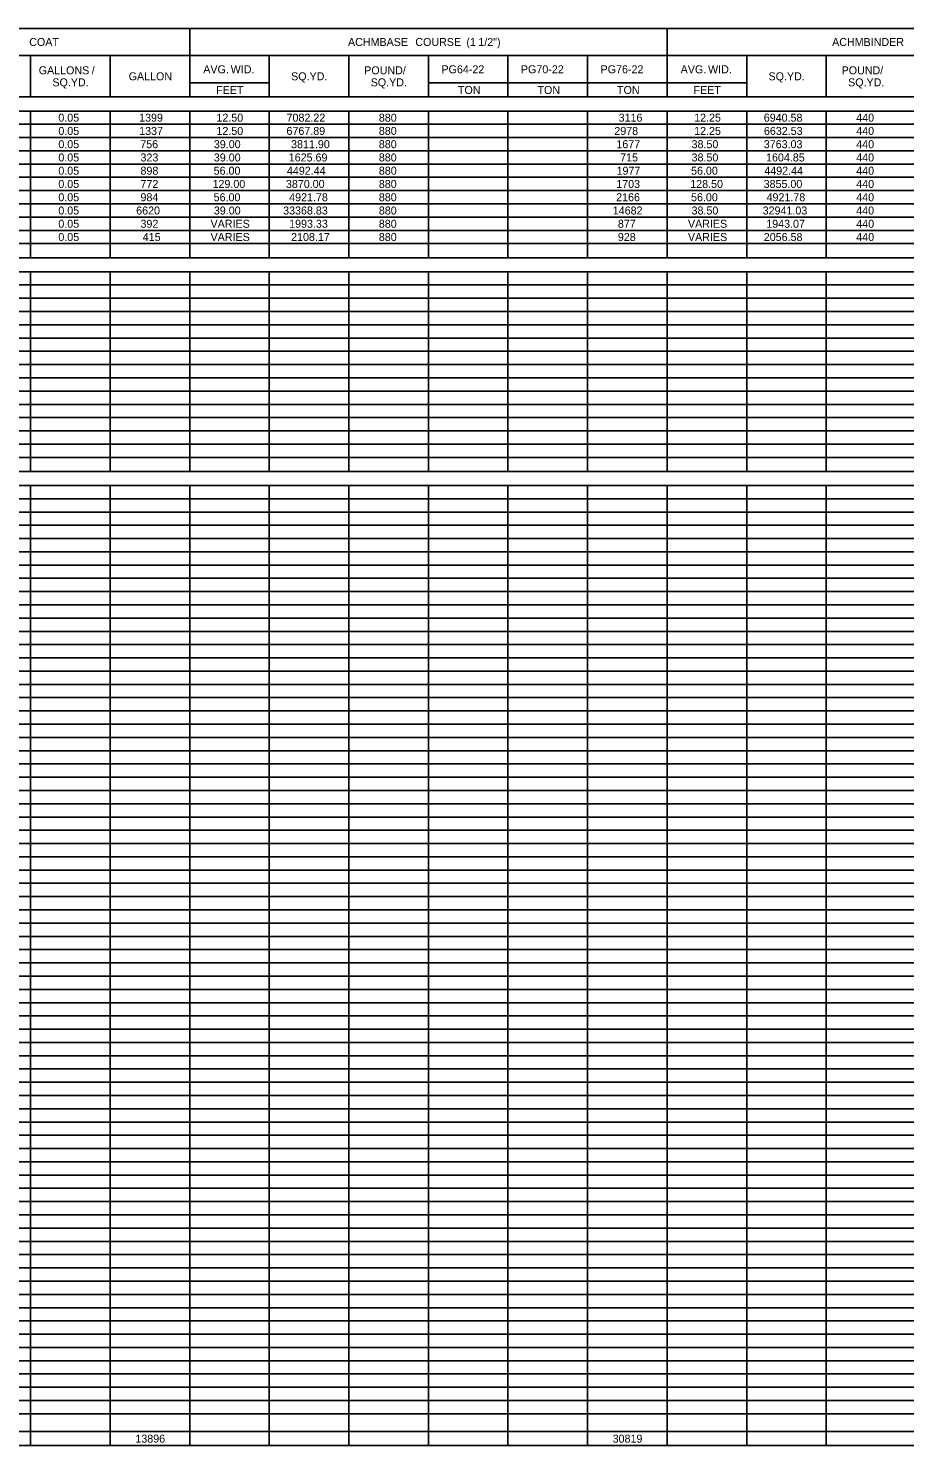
# Model space of a CAD drawing. Extents: x 1226590 to 1228573, y 151304 to 154224.
# Drawn here: x 1227054 to 1227485, y 151485 to 152182 of the extents above; entities that cross this region are included whole.
import ezdxf

# ---------------------------------------------------------------- set-up
doc = ezdxf.new("R2010")
doc.units = 0
doc.layers.add('R_Dimension', color=7, linetype='Continuous')

msp = doc.modelspace()

# ---------------------------------------------------------------- linework, layer by layer
at = {"layer": 'R_Dimension'}
for p, q in [((1226590.27, 152182.03), (1228150.73, 152182.03)), ((1227133.19, 152148.27), (1227133.19, 152182.03)), ((1227368.01, 152148.27), (1227368.01, 152182.03)), ((1226898.37, 152168.6), (1228150.73, 152168.6)), ((1227054.92, 152148.27), (1227054.92, 152168.6)), ((1227094.05, 152148.27), (1227094.05, 152168.6)), ((1227172.32, 152148.27), (1227172.32, 152168.6)), ((1227211.46, 152148.27), (1227211.46, 152168.6)), ((1227250.6, 152148.27), (1227250.6, 152168.6)), ((1227289.73, 152148.27), (1227289.73, 152168.6)), ((1227328.87, 152148.27), (1227328.87, 152168.6)), ((1227407.14, 152148.27), (1227407.14, 152168.6)), ((1227446.28, 152148.27), (1227446.28, 152168.6)), ((1227133.19, 152155.17), (1227172.32, 152155.17)), ((1227250.6, 152155.17), (1227407.14, 152155.17)), ((1226590.27, 152148.27), (1228150.73, 152148.27)), ((1227015.78, 152148.27), (1227172.32, 152148.27)), ((1227172.32, 152148.27), (1227407.14, 152148.27)), ((1227407.14, 152148.27), (1227641.96, 152148.27)), ((1226590.27, 152141.36), (1228150.73, 152141.36)), ((1227054.92, 152069.23), (1227054.92, 152141.36)), ((1227094.05, 152069.23), (1227094.05, 152141.36)), ((1227133.19, 152069.23), (1227133.19, 152141.36)), ((1227172.32, 152069.23), (1227172.32, 152141.36)), ((1227211.46, 152069.23), (1227211.46, 152141.36)), ((1227250.6, 152069.23), (1227250.6, 152141.36)), ((1227289.73, 152069.23), (1227289.73, 152141.36)), ((1227328.87, 152069.23), (1227328.87, 152141.36)), ((1227368.01, 152069.23), (1227368.01, 152141.36)), ((1227407.14, 152069.23), (1227407.14, 152141.36)), ((1227446.28, 152069.23), (1227446.28, 152141.36)), ((1226590.27, 152134.84), (1228150.73, 152134.84)), ((1226590.27, 152128.31), (1228150.73, 152128.31)), ((1226590.27, 152121.79), (1228150.73, 152121.79)), ((1226590.27, 152115.27), (1228150.73, 152115.27)), ((1226590.27, 152108.75), (1228150.73, 152108.75)), ((1226590.27, 152102.22), (1228150.73, 152102.22)), ((1226590.27, 152095.7), (1228150.73, 152095.7)), ((1226590.27, 152089.18), (1228150.73, 152089.18)), ((1226590.27, 152082.65), (1228150.73, 152082.65)), ((1226590.27, 152076.13), (1228150.73, 152076.13)), ((1226590.27, 152069.23), (1228150.73, 152069.23)), ((1226590.27, 152062.32), (1228150.73, 152062.32)), ((1227054.92, 151964.1), (1227054.92, 152062.32)), ((1227094.05, 151964.1), (1227094.05, 152062.32)), ((1227133.19, 151964.1), (1227133.19, 152062.32)), ((1227172.32, 151964.1), (1227172.32, 152062.32)), ((1227211.46, 151964.1), (1227211.46, 152062.32)), ((1227250.6, 151964.1), (1227250.6, 152062.32)), ((1227289.73, 151964.1), (1227289.73, 152062.32)), ((1227328.87, 151964.1), (1227328.87, 152062.32)), ((1227368.01, 151964.1), (1227368.01, 152062.32)), ((1227407.14, 151964.1), (1227407.14, 152062.32)), ((1227446.28, 151964.1), (1227446.28, 152062.32)), ((1226590.27, 152055.8), (1228150.73, 152055.8)), ((1226590.27, 152049.27), (1228150.73, 152049.27)), ((1226590.27, 152042.75), (1228150.73, 152042.75)), ((1226590.27, 152036.23), (1228150.73, 152036.23)), ((1226590.27, 152029.71), (1228150.73, 152029.71)), ((1226590.27, 152023.18), (1228150.73, 152023.18)), ((1226590.27, 152016.66), (1228150.73, 152016.66)), ((1226590.27, 152010.14), (1228150.73, 152010.14)), ((1226590.27, 152003.61), (1228150.73, 152003.61)), ((1226590.27, 151997.09), (1228150.73, 151997.09)), ((1226590.27, 151990.57), (1228150.73, 151990.57)), ((1226590.27, 151984.05), (1228150.73, 151984.05)), ((1226590.27, 151977.52), (1228150.73, 151977.52)), ((1226590.27, 151971), (1228150.73, 151971)), ((1226590.27, 151964.1), (1228150.73, 151964.1)), ((1226590.27, 151957.19), (1228150.73, 151957.19)), ((1227054.92, 151484.92), (1227054.92, 151957.19)), ((1227094.05, 151484.92), (1227094.05, 151957.19)), ((1227133.19, 151484.92), (1227133.19, 151957.19)), ((1227172.32, 151484.92), (1227172.32, 151957.19)), ((1227211.46, 151484.92), (1227211.46, 151957.19)), ((1227250.6, 151484.92), (1227250.6, 151957.19)), ((1227289.73, 151484.92), (1227289.73, 151957.19)), ((1227328.87, 151484.92), (1227328.87, 151957.19)), ((1227368.01, 151484.92), (1227368.01, 151957.19)), ((1227407.14, 151484.92), (1227407.14, 151957.19)), ((1227446.28, 151484.92), (1227446.28, 151957.19)), ((1226590.27, 151950.67), (1228150.73, 151950.67)), ((1226590.27, 151944.14), (1228150.73, 151944.14)), ((1226590.27, 151937.62), (1228150.73, 151937.62)), ((1226590.27, 151931.1), (1228150.73, 151931.1)), ((1226590.27, 151924.58), (1228150.73, 151924.58)), ((1226590.27, 151918.05), (1228150.73, 151918.05)), ((1226590.27, 151911.53), (1228150.73, 151911.53)), ((1226590.27, 151905.01), (1228150.73, 151905.01)), ((1226590.27, 151898.48), (1228150.73, 151898.48)), ((1226590.27, 151891.96), (1228150.73, 151891.96)), ((1226590.27, 151885.44), (1228150.73, 151885.44)), ((1226590.27, 151878.92), (1228150.73, 151878.92)), ((1226590.27, 151872.39), (1228150.73, 151872.39)), ((1226590.27, 151865.87), (1228150.73, 151865.87)), ((1226590.27, 151859.35), (1228150.73, 151859.35)), ((1226590.27, 151852.83), (1228150.73, 151852.83)), ((1226590.27, 151846.3), (1228150.73, 151846.3)), ((1226590.27, 151839.78), (1228150.73, 151839.78)), ((1226590.27, 151833.26), (1228150.73, 151833.26)), ((1226590.27, 151826.73), (1228150.73, 151826.73)), ((1226590.27, 151820.21), (1228150.73, 151820.21)), ((1226590.27, 151813.69), (1228150.73, 151813.69)), ((1226590.27, 151807.17), (1228150.73, 151807.17)), ((1226590.27, 151800.64), (1228150.73, 151800.64)), ((1226590.27, 151794.12), (1228150.73, 151794.12)), ((1226590.27, 151787.6), (1228150.73, 151787.6)), ((1226590.27, 151781.08), (1228150.73, 151781.08)), ((1226590.27, 151774.55), (1228150.73, 151774.55)), ((1226590.27, 151768.03), (1228150.73, 151768.03)), ((1226590.27, 151761.51), (1228150.73, 151761.51)), ((1226590.27, 151754.99), (1228150.73, 151754.99)), ((1226590.27, 151748.46), (1228150.73, 151748.46)), ((1226590.27, 151741.94), (1228150.73, 151741.94)), ((1226590.27, 151735.42), (1228150.73, 151735.42)), ((1226590.27, 151728.89), (1228150.73, 151728.89)), ((1226590.27, 151722.37), (1228150.73, 151722.37)), ((1226590.27, 151715.85), (1228150.73, 151715.85)), ((1226590.27, 151709.33), (1228150.73, 151709.33)), ((1226590.27, 151702.8), (1228150.73, 151702.8)), ((1226590.27, 151696.28), (1228150.73, 151696.28)), ((1226590.27, 151689.76), (1228150.73, 151689.76)), ((1226590.27, 151683.24), (1228150.73, 151683.24)), ((1226590.27, 151676.71), (1228150.73, 151676.71)), ((1226590.27, 151670.19), (1228150.73, 151670.19)), ((1226590.27, 151663.67), (1228150.73, 151663.67)), ((1226590.27, 151657.14), (1228150.73, 151657.14)), ((1226590.27, 151650.62), (1228150.73, 151650.62)), ((1226590.27, 151644.1), (1228150.73, 151644.1)), ((1226590.27, 151637.58), (1228150.73, 151637.58)), ((1226590.27, 151631.05), (1228150.73, 151631.05)), ((1226590.27, 151624.53), (1228150.73, 151624.53)), ((1226590.27, 151618.01), (1228150.73, 151618.01)), ((1226590.27, 151611.49), (1228150.73, 151611.49)), ((1226590.27, 151604.96), (1228150.73, 151604.96)), ((1226590.27, 151598.44), (1228150.73, 151598.44)), ((1226590.27, 151591.92), (1228150.73, 151591.92)), ((1226590.27, 151585.4), (1228150.73, 151585.4)), ((1226590.27, 151578.87), (1228150.73, 151578.87)), ((1226590.27, 151572.35), (1228150.73, 151572.35)), ((1226590.27, 151565.83), (1228150.73, 151565.83)), ((1226590.27, 151559.3), (1228150.73, 151559.3)), ((1226590.27, 151552.78), (1228150.73, 151552.78)), ((1226590.27, 151546.26), (1228150.73, 151546.26)), ((1226590.27, 151539.74), (1228150.73, 151539.74)), ((1226590.27, 151533.21), (1228150.73, 151533.21)), ((1226590.27, 151526.69), (1228150.73, 151526.69)), ((1226590.27, 151520.17), (1228150.73, 151520.17)), ((1226590.27, 151513.65), (1228150.73, 151513.65)), ((1226590.27, 151507.12), (1228150.73, 151507.12)), ((1226590.27, 151500.6), (1228150.73, 151500.6)), ((1226590.27, 151491.83), (1228150.75, 151491.83)), ((1226590.27, 151484.92), (1228150.75, 151484.92))]:
    msp.add_line(p, q, dxfattribs=at)

# ---------------------------------------------------------------- texts
for s, p in [(' COAT', (1227052.78, 152173.35)), ('ACHM', (1227211.06, 152173.35)), (' BASE', (1227225.06, 152173.35)), (' COURSE', (1227242.7, 152173.35)), (' (1', (1227267.83, 152173.35)), (' 1/2")', (1227273.68, 152173.35)), ('ACHM', (1227449.16, 152173.35)), (' BINDER', (1227463.17, 152173.35)), ('GALLONS', (1227058.93, 152159.42)), (' /', (1227083.53, 152159.42)), ('GALLON', (1227103.16, 152156.47)), ('AVG.', (1227139.85, 152159.92)), (' WID.', (1227151.87, 152159.92)), ('SQ.YD.', (1227183.06, 152156.47)), ('POUND', (1227219.02, 152159.42)), (' /', (1227236.53, 152159.42)), ('PG', (1227257, 152159.92)), (' 64-22', (1227263.16, 152159.92)), ('PG', (1227296.07, 152159.92)), (' 70-22', (1227302.24, 152159.92)), ('PG', (1227335.27, 152159.92)), (' 76-22', (1227341.43, 152159.92)), ('AVG.', (1227374.67, 152159.92)), (' WID.', (1227386.69, 152159.92)), ('SQ.YD.', (1227417.88, 152156.47)), ('POUND', (1227453.84, 152159.42)), (' /', (1227471.35, 152159.42)), ('SQ.YD.', (1227065.65, 152153.51)), ('FEET', (1227146.17, 152149.75)), ('SQ.YD.', (1227222.2, 152153.51)), ('TON', (1227265.1, 152149.75)), ('TON', (1227304.23, 152149.75)), ('TON', (1227343.37, 152149.75)), ('FEET', (1227380.99, 152149.75)), ('SQ.YD.', (1227457.01, 152153.51)), ('0.05', (1227068.57, 152136.13)), ('1399', (1227108.31, 152136.13)), ('12.50', (1227146.33, 152136.13)), ('7082.22', (1227180.83, 152136.13)), ('880', (1227226.21, 152136.13)), ('3116', (1227344.15, 152136.13)), ('12.25', (1227381.31, 152136.13)), ('6940.58', (1227415.55, 152136.13)), ('440', (1227461.03, 152136.13)), ('0.05', (1227068.57, 152129.61)), ('1337', (1227108.32, 152129.61)), ('12.50', (1227146.33, 152129.61)), ('6767.89', (1227180.78, 152129.61)), ('880', (1227226.21, 152129.61)), ('2978', (1227342.02, 152129.61)), ('12.25', (1227381.31, 152129.61)), ('6632.53', (1227415.62, 152129.61)), ('440', (1227461.03, 152129.61)), ('0.05', (1227068.57, 152123.08)), ('756', (1227108.86, 152123.08)), ('39.00', (1227145.06, 152123.08)), ('3811.90', (1227183.05, 152123.08)), ('880', (1227226.21, 152123.08)), ('1677', (1227343.05, 152123.08)), ('38.50', (1227380.03, 152123.08)), ('3763.03', (1227415.55, 152123.08)), ('440', (1227461.03, 152123.08)), ('0.05', (1227068.57, 152116.56)), ('323', (1227108.97, 152116.56)), ('39.00', (1227145.06, 152116.56)), ('1625.69', (1227181.9, 152116.56)), ('880', (1227226.21, 152116.56)), ('715', (1227344.9, 152116.56)), ('38.50', (1227380.03, 152116.56)), ('1604.85', (1227416.67, 152116.56)), ('440', (1227461.03, 152116.56)), ('0.05', (1227068.57, 152110.04)), ('898', (1227108.97, 152110.04)), ('56.00', (1227144.96, 152110.04)), ('4492.44', (1227180.99, 152110.04)), ('880', (1227226.21, 152110.04)), ('1977', (1227343.14, 152110.04)), ('56.00', (1227379.78, 152110.04)), ('4492.44', (1227415.8, 152110.04)), ('440', (1227461.03, 152110.04)), ('0.05', (1227068.57, 152103.52)), ('772', (1227108.97, 152103.52)), ('129.00', (1227144.41, 152103.52)), ('3870.00', (1227180.51, 152103.52)), ('880', (1227226.21, 152103.52)), ('1703', (1227342.98, 152103.52)), ('128.50', (1227379.38, 152103.52)), ('3855.00', (1227415.48, 152103.52)), ('440', (1227461.03, 152103.52)), ('0.05', (1227068.57, 152096.99)), ('984', (1227108.97, 152096.99)), ('56.00', (1227144.96, 152096.99)), ('4921.78', (1227182.1, 152096.99)), ('880', (1227226.21, 152096.99)), ('2166', (1227342.94, 152096.99)), ('56.00', (1227379.78, 152096.99)), ('4921.78', (1227416.92, 152096.99)), ('440', (1227461.03, 152096.99)), ('0.05', (1227068.57, 152090.47)), ('6620', (1227106.85, 152090.47)), ('39.00', (1227145.06, 152090.47)), ('33368.83', (1227179.13, 152090.47)), ('880', (1227226.21, 152090.47)), ('14682', (1227341.28, 152090.47)), ('38.50', (1227380.03, 152090.47)), ('32941.03', (1227415, 152090.47)), ('440', (1227461.03, 152090.47)), ('0.05', (1227068.57, 152083.95)), ('392', (1227108.97, 152083.95)), ('VARIES', (1227143.43, 152083.95)), ('1993.33', (1227182.1, 152083.95)), ('880', (1227226.21, 152083.95)), ('877', (1227343.79, 152083.95)), ('VARIES', (1227378.25, 152083.95)), ('1943.07', (1227416.76, 152083.95)), ('440', (1227461.03, 152083.95)), ('0.05', (1227068.57, 152077.43)), ('415', (1227110.09, 152077.43)), ('VARIES', (1227143.43, 152077.43)), ('2108.17', (1227183.06, 152077.43)), ('880', (1227226.21, 152077.43)), ('928', (1227343.79, 152077.43)), ('VARIES', (1227378.25, 152077.43)), ('2056.58', (1227415.55, 152077.43)), ('440', (1227461.03, 152077.43)), ('13896', (1227106.46, 151486.4)), ('30819', (1227341.21, 151486.4))]:
    msp.add_text(s, height=3.935, dxfattribs=at).set_placement(p)

doc.saveas('drawing.dxf')
